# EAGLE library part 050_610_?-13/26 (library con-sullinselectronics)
.050 DIP EDGE CARD CONNECTOR .050 [1.27mm] CONTACT CENTERS .610" INSULATEOR HEIGHT Source: .050 DIP EDGE CARD.pdf
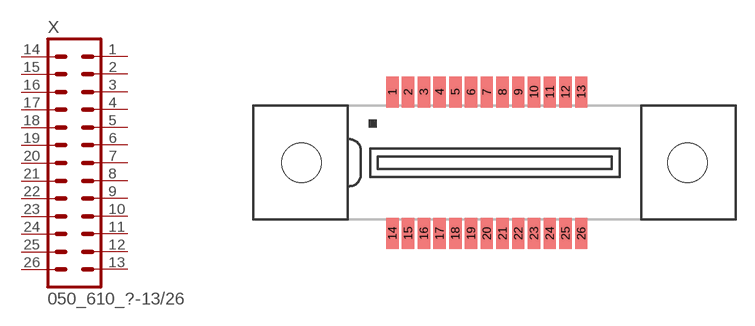
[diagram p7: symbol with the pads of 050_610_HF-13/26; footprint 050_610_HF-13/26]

Designator prefix X

## 050_610_HF-13/26 (OC_FARNELL: unknown; OC_NEWARK: unknown)  [050_610_HF-13/26]
1  1  pas
2  2  pas
3  3  pas
4  4  pas
5  5  pas
6  6  pas
7  7  pas
8  8  pas
9  9  pas
10  10  pas
11  11  pas
12  12  pas
13  13  pas
14  14  pas
15  15  pas
16  16  pas
17  17  pas
18  18  pas
19  19  pas
20  20  pas
21  21  pas
22  22  pas
23  23  pas
24  24  pas
25  25  pas
26  26  pas

## Footprint 050_610_HF-13/26 (pad centres in mm)
.050 DIP EDGE CARD CONNECTOR SURFACE MOUNT .050 [1.27mm] CONTACT CENTERS .610" INSULATEOR HEIGHT Source: .050 DIP EDGE CARD.pdf
smd 1 x 2.5: 1 -7.62,5.715; 2 -6.35,5.715; 3 -5.08,5.715; 4 -3.81,5.715; 5 -2.54,5.715; 6 -1.27,5.715; 7 0,5.715; 8 1.27,5.715; 9 2.54,5.715; 10 3.81,5.715; 11 5.08,5.715; 12 6.35,5.715; 13 7.62,5.715; 14 -7.62,-5.715; 15 -6.35,-5.715; 16 -5.08,-5.715; 17 -3.81,-5.715; 18 -2.54,-5.715; 19 -1.27,-5.715; 20 0,-5.715; 21 1.27,-5.715; 22 2.54,-5.715; 23 3.81,-5.715; 24 5.08,-5.715; 25 6.35,-5.715; 26 7.62,-5.715
hole 3.18 at -14.935,0
hole 3.18 at 16.205,0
